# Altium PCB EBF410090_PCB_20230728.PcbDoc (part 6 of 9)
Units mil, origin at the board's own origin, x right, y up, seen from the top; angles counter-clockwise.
Board outline 5393.69 x 3858.26 mil, 6 copper layers (TOP, GND02, ART03, ART04, PWR05, BOTTOM), stack 47.2 mil thick; 570 components, 437 nets, 2015 pads, 1260 vias.
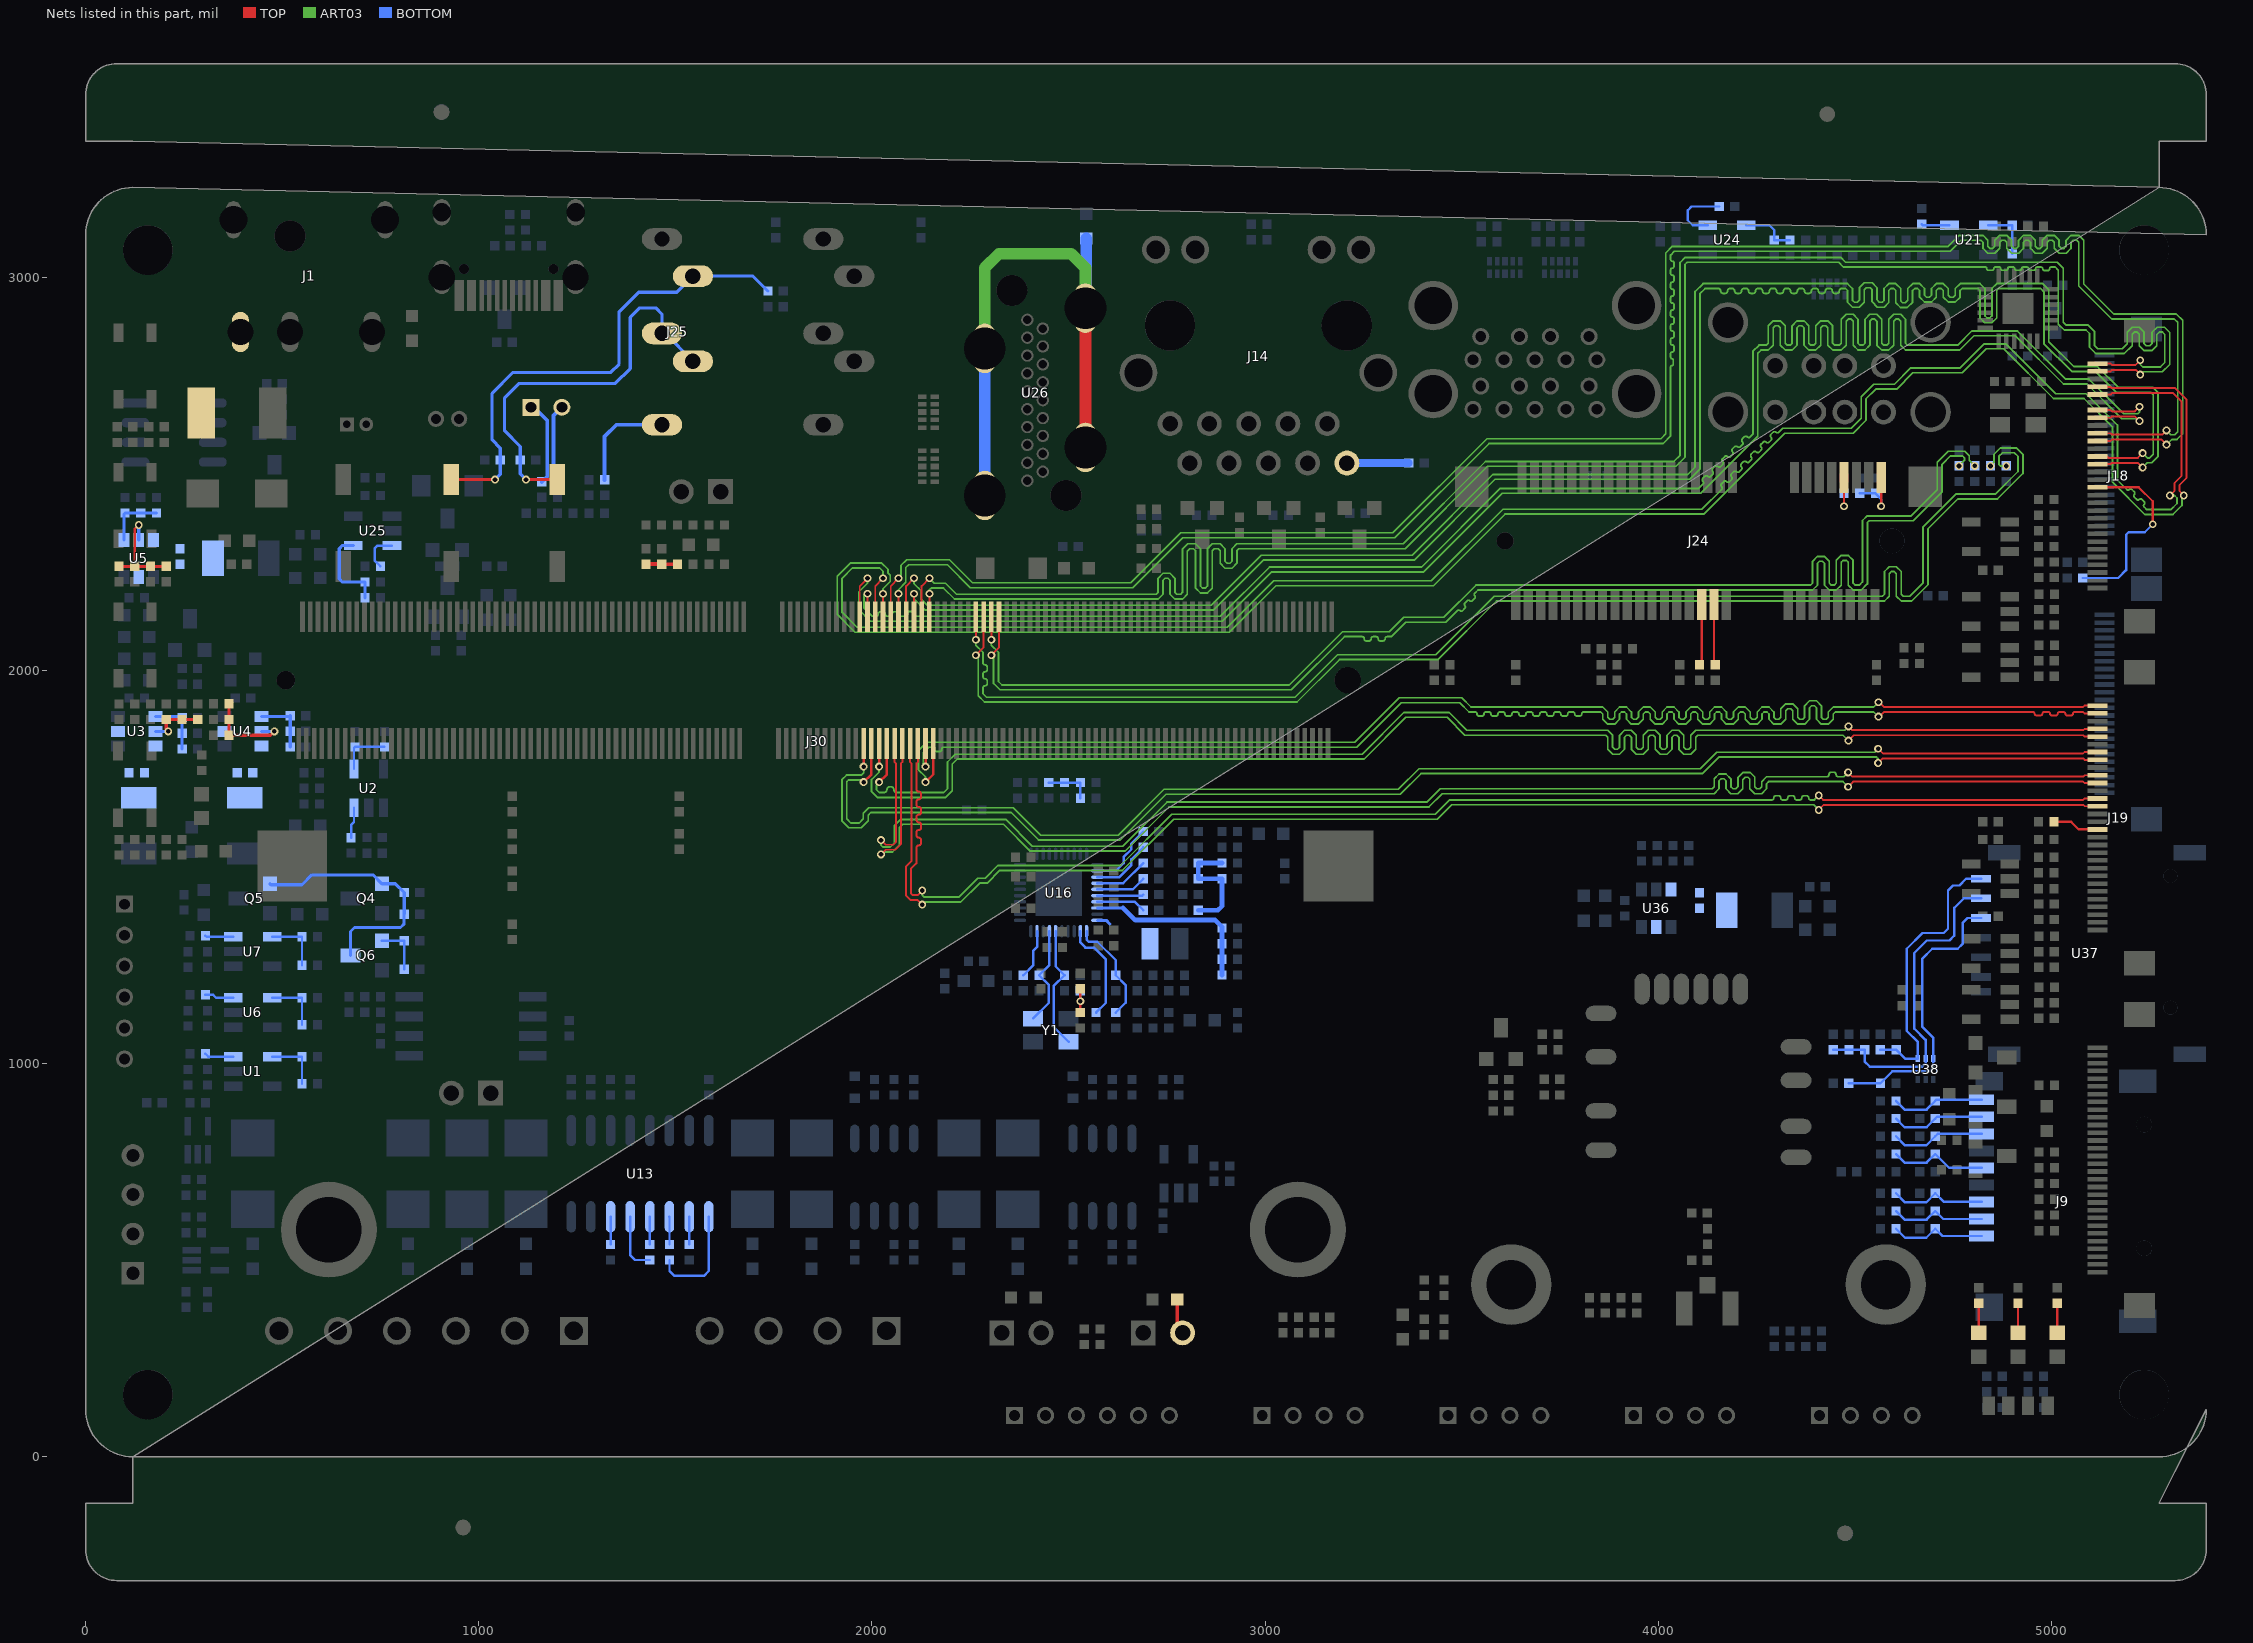
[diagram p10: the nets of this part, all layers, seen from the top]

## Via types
v1: diameter 20, hole 12, TOP to BOTTOM, 1260 vias

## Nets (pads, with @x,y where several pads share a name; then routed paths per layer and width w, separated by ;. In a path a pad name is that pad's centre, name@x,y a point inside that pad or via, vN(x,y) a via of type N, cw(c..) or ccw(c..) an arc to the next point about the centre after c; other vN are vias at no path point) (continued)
MIPI_CSI_RX_D2N: J30.91 R179.1 R181.1 | length 3498.5
  TOP w4.88: v1(2264.25,2038.7) 2283.93,2058.38 J30.91@2283.93,2136.54
  ART03 w4.44: v1(2264.25,2038.7) 2270.03,2032.92 2270.03,1935.72 2286.19,1919.56 3081.16,1919.56 3189.16,2027.56 3439.56,2027.56 3588.46,2176.46 4575.33,2176.46 4587.81,2188.94 4587.81,2246.36 4593.01,2251.56 4600.37,2251.56 4605.57,2246.36 4605.57,2188.94 4618.05,2176.46 4644.46,2176.46 4686,2218 4686,2360.4 4761.6,2436 4862.6,2436 4927.44,2500.84 4927.44,2549.56 4911,2566 4870.5,2566 4854,2549.5 4854,2528.68 v1(4845,2519.68)
MIPI_CSI_RX_D2P: J30.93 R177.1 R178.1 | length 3449.3
  TOP w4.88: v1(2264.25,2078.07) J30.93@2264.25,2136.54
  ART03 w4.44: v1(2264.25,2078.07) 2264.25,2064.47 2282.47,2046.25 2282.47,2019.45 ccw(c2287.73,2019.45) 2287.73,2014.19 cw(c2287.74,2008.93) 2293,2008.93 2293,2001.69 cw(c2287.74,2001.69) 2287.74,1996.43 ccw(c2287.73,1991.17) 2282.47,1991.17 2282.47,1983.93 ccw(c2287.73,1983.93) 2287.73,1978.67 cw(c2287.74,1973.41) 2293,1973.41 2293,1966.17 cw(c2287.74,1966.17) 2287.74,1960.91 ccw(c2287.73,1955.65) 2282.47,1955.65 2282.47,1940.88 2291.35,1932 3076,1932 3184,2040 3434.4,2040 3583.3,2188.9 4570.17,2188.9 4575.37,2194.1 4575.37,2251.52 4587.85,2264 4605.53,2264 4618.01,2251.52 4618.01,2194.1 4623.21,2188.9 4639.3,2188.9 4673.56,2223.16 4673.56,2365.56 4756.44,2448.44 4857.44,2448.44 4915,2506 4915,2544.4 4905.84,2553.56 4875.66,2553.56 4866.44,2544.34 4866.44,2524.22 4870.98,2519.68 v1(4885,2519.68)
MIPI_CSI_RX_D3N: J30.87 R185.1 R186.1 | length 3365.8
  TOP w4.88: v1(2303.62,2038.7) 2323.3,2058.38 J30.87@2323.3,2136.54
  ART03 w4.44: v1(2303.62,2038.7) 2309.4,2032.92 2309.4,1966.72 2325.56,1950.56 3066.56,1950.56 3202,2086 3246.55,2086 cw(c3246.55,2080.5) 3252.05,2080.5 ccw(c3257.55,2080.5) 3257.55,2075 3264.31,2075 ccw(c3264.31,2080.5) 3269.81,2080.5 cw(c3275.31,2080.5) 3275.31,2086 3282.07,2086 cw(c3282.07,2080.5) 3287.57,2080.5 ccw(c3293.07,2080.5) 3293.07,2075 3299.83,2075 ccw(c3299.83,2080.5) 3305.33,2080.5 cw(c3310.83,2080.5) 3310.83,2086 3321,2086 3357.56,2122.56 3459.56,2122.56 3489.03,2152.03 cw(c3492.28,2148.79) 3495.53,2152.03 ccw(c3498.78,2155.27) 3502.03,2152.03 3508.09,2158.09 ccw(c3504.85,2161.34) 3508.09,2164.59 cw(c3511.33,2167.84) 3508.09,2171.09 3514.15,2177.15 cw(c3517.4,2173.91) 3520.65,2177.15 ccw(c3523.9,2180.39) 3527.15,2177.15 3533.21,2183.21 ccw(c3529.97,2186.46) 3533.21,2189.71 cw(c3536.45,2192.96) 3533.21,2196.21 3541.56,2204.56 4392.46,2204.56 4404.94,2217.04 4404.94,2272.36 4410.14,2277.56 4417.5,2277.56 4422.7,2272.36 4422.7,2217.04 4435.18,2204.56 4452.86,2204.56 4465.34,2217.04 4465.34,2275.12 4469.78,2279.56 4478.66,2279.56 4483.1,2275.12 4483.1,2217.04 4495.58,2204.56 4516.56,2204.56 4532,2220 4532,2376.12 4536.44,2380.56 4648.55,2380.56 4722,2454.01 4722,2524.4 4742.88,2545.28 4774.34,2545.28 4778.78,2540.84 4778.78,2534.1 4765,2520.32 v1(4765,2519.68)
MIPI_CSI_RX_D3P: J30.89 R183.1 R184.1 | length 3316
  TOP w4.88: v1(2303.62,2078.07) J30.89@2303.62,2136.54
  ART03 w4.44: v1(2303.62,2078.07) 2303.62,2064.47 2321.84,2046.25 2321.84,1971.88 2330.72,1963 3061.4,1963 3196.84,2098.44 3315.84,2098.44 3352.4,2135 3454.4,2135 3536.4,2217 4387.3,2217 4392.5,2222.2 4392.5,2277.52 4404.98,2290 4422.66,2290 4435.14,2277.52 4435.14,2222.2 4440.34,2217 4447.7,2217 4452.9,2222.2 4452.9,2280.28 4464.62,2292 4483.82,2292 4495.54,2280.28 4495.54,2222.2 4500.74,2217 4511.4,2217 4519.56,2225.16 4519.56,2381.28 4531.28,2393 4643.39,2393 4709.56,2459.17 4709.56,2529.56 4737.72,2557.72 4779.5,2557.72 4791.22,2546 4791.22,2534.1 v1(4805,2520.32)
MIPI_DSI_TX0_CLKN: J18.24 J30.121 | length 4810.6
  TOP w4.88: J30.121@1988.66,2136.54 v1(1988.66,2195.01) ; J18.24@5117.47,2662.33 5150.56,2662.33 5153.96,2658.93 5212.18,2658.93 v1(5224,2670.75)
  ART03 w4.44: v1(1988.66,2195.01) 1983.88,2195.01 1979.44,2190.57 1979.44,2159.16 2000.8,2137.8 2010.24,2137.8 ccw(c2010.24,2143.4) 2015.84,2143.4 cw(c2021.44,2143.4) 2021.44,2149 2028,2149 cw(c2028,2143.4) 2033.6,2143.4 ccw(c2039.2,2143.4) 2039.2,2137.8 2045.76,2137.8 ccw(c2045.76,2143.4) 2051.36,2143.4 cw(c2056.96,2143.4) 2056.96,2149 2063.52,2149 cw(c2063.52,2143.4) 2069.12,2143.4 ccw(c2074.72,2143.4) 2074.72,2137.8 2084.16,2137.8 ccw(c2084.16,2143.9) 2090.26,2143.9 cw(c2096.36,2143.9) 2096.36,2150 2101.92,2150 cw(c2101.92,2143.9) 2108.02,2143.9 ccw(c2114.12,2143.9) 2114.12,2137.8 2886.2,2137.8 3011.4,2263 3398,2263 3598,2463 4103,2463 4113.49,2473.49 ccw(c4109.74,2477.24) 4113.48,2480.99 cw(c4117.23,2484.74) 4113.48,2488.49 4118.54,2493.55 cw(c4122.29,2489.8) 4126.04,2493.55 ccw(c4129.8,2497.29) 4133.55,2493.55 4138.61,2498.61 ccw(c4134.86,2502.36) 4138.6,2506.11 cw(c4142.35,2509.86) 4138.6,2513.61 4143.66,2518.67 cw(c4147.41,2514.92) 4151.16,2518.67 ccw(c4154.92,2522.41) 4158.67,2518.67 4163.73,2523.73 ccw(c4159.98,2527.48) 4163.72,2531.23 cw(c4167.47,2534.98) 4163.72,2538.73 4168.78,2543.79 cw(c4172.53,2540.04) 4176.28,2543.79 ccw(c4180.04,2547.53) 4183.79,2543.79 4188.85,2548.85 ccw(c4185.1,2552.6) 4188.84,2556.35 cw(c4192.59,2560.1) 4188.84,2563.85 4193.9,2568.91 cw(c4197.65,2565.16) 4201.4,2568.91 ccw(c4205.16,2572.65) 4208.91,2568.91 4213.97,2573.97 ccw(c4210.22,2577.72) 4213.96,2581.47 cw(c4217.71,2585.22) 4213.96,2588.97 4219.02,2594.03 cw(c4222.77,2590.28) 4226.52,2594.03 ; 4226.53,2594.02 ccw(c4230.28,2597.77) 4234.03,2594.03 4240.72,2600.72 4240.72,2811.72 4256.44,2827.44 4274.86,2827.44 4280.06,2832.64 4280.06,2876.52 4292.54,2889 4310.22,2889 4322.7,2876.52 4322.7,2832.64 4327.9,2827.44 4335.26,2827.44 4340.46,2832.64 4340.46,2876.52 4352.94,2889 4370.62,2889 4383.1,2876.52 4383.1,2832.64 4388.3,2827.44 4395.66,2827.44 4400.86,2832.64 4400.86,2876.52 4413.34,2889 4431.02,2889 4443.5,2876.52 4443.5,2832.64 4448.7,2827.44 4460.27,2827.44 4465.47,2832.64 4465.47,2893.52 4477.95,2906 4495.63,2906 4508.11,2893.52 4508.11,2832.64 4513.31,2827.44 4520.67,2827.44 4525.87,2832.64 4525.87,2893.52 4538.35,2906 4556.03,2906 4568.51,2893.52 4568.51,2832.64 4573.71,2827.44 4581.07,2827.44 4586.27,2832.64 4586.27,2893.52 4598.75,2906 4616.43,2906 4628.91,2893.52 4628.91,2832.64 4634.11,2827.44 4761.84,2827.44 4797.84,2863.44 4913.56,2863.44 5036,2741 5095.6,2741 5183.89,2652.71 5219.56,2652.71 5224,2657.15 v1(5224,2670.75)
MIPI_DSI_TX0_CLKP: J18.23 J30.123 | length 4807.4
  TOP w4.88: J30.123@1968.97,2136.54 1968.97,2214.69 v1(1988.66,2234.38) ; J18.23@5117.47,2642.64 5150.55,2642.64 5153.96,2646.05 5212.19,2646.05 v1(5224,2634.24)
  ART03 w4.44: v1(1988.66,2234.38) 1988.66,2221.66 1967,2200 1967,2154 1995.64,2125.36 2891.36,2125.36 3016.56,2250.56 3403.16,2250.56 3603.16,2450.56 4108.16,2450.56 4253.16,2595.56 4253.16,2806.56 4261.6,2815 4280.02,2815 4292.5,2827.48 4292.5,2871.36 4297.7,2876.56 4305.06,2876.56 4310.26,2871.36 4310.26,2827.48 4322.74,2815 4340.42,2815 4352.9,2827.48 4352.9,2871.36 4358.1,2876.56 4365.46,2876.56 4370.66,2871.36 4370.66,2827.48 4383.14,2815 4400.82,2815 4413.3,2827.48 4413.3,2871.36 4418.5,2876.56 4425.86,2876.56 4431.06,2871.36 4431.06,2827.48 4443.54,2815 4465.43,2815 4477.91,2827.48 4477.91,2888.36 4483.11,2893.56 4490.47,2893.56 4495.67,2888.36 4495.67,2827.48 4508.15,2815 4525.83,2815 4538.31,2827.48 4538.31,2888.36 4543.51,2893.56 4550.87,2893.56 4556.07,2888.36 4556.07,2827.48 4568.55,2815 4586.23,2815 4598.71,2827.48 4598.71,2888.36 4603.91,2893.56 4611.27,2893.56 4616.47,2888.36 4616.47,2827.48 4628.95,2815 4767,2815 4803,2851 4908.4,2851 5030.84,2728.56 5090.44,2728.56 5178.73,2640.27 5217.97,2640.27 v1(5224,2634.24)
MIPI_DSI_TX0_D0N: J18.27 J30.117 | length 4936.3
  TOP w4.88: J30.117@2028.03,2136.54 v1(2028.03,2195.01) ; J18.27@5117.47,2721.38 5150.56,2721.38 5153.96,2717.98 5315.02,2717.98 5344.14,2688.86 5344.14,2490.14 5326,2472 5326,2455.87 v1(5336.69,2445.18)
  ART03 w4.44: v1(2028.03,2195.01) 2028.03,2208.03 2046.25,2226.25 2046.25,2231.61 2046.26,2241.92 2041,2247.18 2041,2256.6 2024.6,2273 1945,2273 1911.56,2239.56 1911.56,2142.44 1956.74,2097.26 2909.26,2097.26 3027.56,2215.56 3428.16,2215.56 3610.16,2397.56 4116.16,2397.56 4322.16,2603.56 4495.56,2603.56 4528.44,2636.44 4528.44,2690.84 4553.16,2715.56 4606.15,2715.56 4647.59,2757 4773,2757 4834,2818 4879,2818 5005.44,2691.56 5082.84,2691.56 5155.56,2618.84 5155.56,2478.44 5237.44,2396.56 5309.07,2396.56 5332,2419.49 5332,2440.49 v1(5336.69,2445.18)
MIPI_DSI_TX0_D0P: J18.26 J30.119 | length 4937.7
  TOP w4.88: J30.119@2008.34,2136.54 2008.34,2214.69 v1(2028.03,2234.38) ; J18.26@5117.47,2701.7 5150.56,2701.7 5153.96,2705.1 5309.68,2705.1 5331.26,2683.52 5331.26,2495.48 5313.12,2477.34 5313.12,2456.99 v1(5301.31,2445.18)
  ART03 w4.44: v1(2028.03,2234.38) 2028.03,2251.97 2019.44,2260.56 1950.16,2260.56 1924,2234.4 1924,2147.6 1961.9,2109.7 2904.1,2109.7 3022.4,2228 3423,2228 3605,2410 4111,2410 4161.14,2460.14 ccw(c4157.39,2463.89) 4161.14,2467.64 cw(c4164.89,2471.39) 4161.14,2475.14 4166.2,2480.2 cw(c4169.95,2476.45) 4173.7,2480.2 ccw(c4177.45,2483.95) 4181.2,2480.2 4186.26,2485.26 ccw(c4182.51,2489.01) 4186.26,2492.76 cw(c4190.01,2496.51) 4186.26,2500.26 4191.32,2505.32 cw(c4195.07,2501.57) 4198.82,2505.32 ccw(c4202.57,2509.07) 4206.32,2505.32 4211.38,2510.38 ccw(c4207.63,2514.13) 4211.38,2517.88 cw(c4215.13,2521.63) 4211.38,2525.38 4216.44,2530.44 cw(c4220.19,2526.69) 4223.94,2530.44 ccw(c4227.69,2534.19) 4231.44,2530.44 4236.5,2535.5 ccw(c4232.75,2539.25) 4236.5,2543 cw(c4240.25,2546.75) 4236.5,2550.5 4241.56,2555.56 cw(c4245.31,2551.81) 4249.06,2555.56 ccw(c4252.81,2559.31) 4256.56,2555.56 4261.62,2560.62 ccw(c4257.87,2564.37) 4261.62,2568.12 cw(c4265.37,2571.87) 4261.62,2575.62 4266.68,2580.68 cw(c4270.43,2576.93) 4274.18,2580.68 ccw(c4277.93,2584.43) 4281.68,2580.68 4286.74,2585.74 ccw(c4282.99,2589.49) 4286.74,2593.24 cw(c4290.49,2596.99) 4286.74,2600.74 4291.8,2605.8 cw(c4295.55,2602.05) 4299.3,2605.8 ccw(c4303.05,2609.55) 4306.8,2605.8 4317,2616 4490.4,2616 4516,2641.6 4516,2696 4548,2728 4600.99,2728 4642.43,2769.44 4767.84,2769.44 4828.84,2830.44 4884.16,2830.44 5010.6,2704 5088,2704 5168,2624 5168,2483.6 5191.54,2460.06 ccw(c5194.88,2463.41) 5198.22,2460.06 ; 5198.24,2460.08 cw(c5201.58,2456.73) 5204.92,2460.08 5210.8,2454.2 cw(c5207.45,2450.86) 5210.8,2447.52 ccw(c5214.13,2444.16) 5210.78,2440.82 5216.66,2434.94 ccw(c5220,2438.29) 5223.34,2434.94 cw(c5226.7,2431.61) 5230.04,2434.96 5235.92,2429.08 cw(c5232.57,2425.74) 5235.92,2422.4 ccw(c5239.25,2419.04) 5235.9,2415.7 5242.6,2409 5303.91,2409 5319.56,2424.65 5319.56,2438.45 5312.83,2445.18 v1(5301.31,2445.18)
MIPI_DSI_TX0_D1N: J18.21 J30.113 | length 4934.4
  TOP w4.88: J30.113@2067.4,2136.54 v1(2067.4,2195.01) ; J18.21@5117.47,2603.27 5150.56,2603.27 5153.96,2599.87 5282.18,2599.87 v1(5293,2610.69)
  ART03 w4.44: v1(2067.4,2195.01) 2067.4,2205.4 2086,2224 2086,2261.68 2093.32,2269 2192,2269 2250.44,2210.56 2663.56,2210.56 2790.56,2337.56 3330.16,2337.56 3569.6,2577 4012,2577 4031.44,2596.44 4031.44,2772.03 cw(c4034.72,2772.03) 4034.72,2775.31 ccw(c4034.72,2778.59) 4038,2778.59 4038,2789.79 ccw(c4034.72,2789.79) 4034.72,2793.07 cw(c4034.72,2796.35) 4031.44,2796.35 4031.44,2805.79 cw(c4035.67,2805.79) 4035.67,2810.02 ccw(c4035.67,2814.25) 4039.9,2814.25 4039.9,2823.55 ccw(c4035.67,2823.55) 4035.67,2827.78 cw(c4035.67,2832.01) 4031.44,2832.01 4031.44,2841.31 cw(c4035.67,2841.31) 4035.67,2845.54 ccw(c4035.67,2849.77) 4039.9,2849.77 4039.9,2859.07 ccw(c4035.67,2859.07) 4035.67,2863.3 cw(c4035.67,2867.53) 4031.44,2867.53 4031.44,2876.83 cw(c4035.67,2876.83) 4035.67,2881.06 ccw(c4035.67,2885.29) 4039.9,2885.29 4039.9,2894.59 ccw(c4035.67,2894.59) 4035.67,2898.82 cw(c4035.67,2903.05) 4031.44,2903.05 4031.44,2912.35 cw(c4035.67,2912.35) 4035.67,2916.58 ccw(c4035.67,2920.81) 4039.9,2920.81 4039.9,2930.11 ccw(c4035.67,2930.11) 4035.67,2934.34 cw(c4035.67,2938.57) 4031.44,2938.57 4031.44,2947.87 cw(c4035.67,2947.87) 4035.67,2952.1 ccw(c4035.67,2956.33) 4039.9,2956.33 4039.9,2965.63 ccw(c4035.67,2965.63) 4035.67,2969.86 cw(c4035.67,2974.09) 4031.44,2974.09 4031.44,2983.39 cw(c4035.67,2983.39) 4035.67,2987.62 ccw(c4035.67,2991.85) 4039.9,2991.85 4039.9,3001.15 ccw(c4035.67,3001.15) 4035.67,3005.38 cw(c4035.67,3009.61) 4031.44,3009.61 4031.44,3018.91 cw(c4035.67,3018.91) 4035.67,3023.14 ccw(c4035.67,3027.37) 4039.9,3027.37 4039.9,3036.67 ccw(c4035.67,3036.67) 4035.67,3040.9 cw(c4035.67,3045.13) 4031.44,3045.13 4031.44,3056.44 4041.1,3066.1 4742.7,3066.1 4770.6,3094 4820.72,3094 4825.92,3088.8 4825.92,3073.48 4838.4,3061 4856.08,3061 4868.56,3073.48 4868.56,3088.8 4873.76,3094 4881.12,3094 4886.32,3088.8 4886.32,3073.48 4898.8,3061 4916.48,3061 4928.96,3073.48 4928.96,3088.8 4934.16,3094 4941.52,3094 4946.72,3088.8 4946.72,3073.48 4959.2,3061 4976.88,3061 4989.36,3073.48 4989.36,3088.8 4994.56,3094 5001.92,3094 5007.12,3088.8 5007.12,3073.48 5019.6,3061 5037.28,3061 5049.76,3073.48 5049.76,3088.8 5054.96,3094 5064.4,3094 5069.56,3088.84 5069.56,2977.84 5153.4,2894 5312.68,2894 5321.56,2885.12 5321.56,2607.17 5314.04,2599.65 5304.04,2599.65 v1(5293,2610.69)
MIPI_DSI_TX0_D1P: J18.20 J30.115 | length 4926.9
  TOP w4.88: J30.115@2047.71,2136.54 2047.71,2214.69 v1(2067.4,2234.38) ; J18.20@5117.47,2583.59 5150.56,2583.59 5153.96,2586.99 5280.19,2586.99 v1(5293,2574.18)
  ART03 w4.44: v1(2067.4,2234.38) 2069.12,2234.38 2073.56,2238.82 2073.56,2266.84 2088.16,2281.44 2197.16,2281.44 2255.6,2223 2658.4,2223 2785.4,2350 3325,2350 3564.44,2589.44 4006.84,2589.44 4019,2601.6 4019,3061.6 4035.94,3078.54 4737.54,3078.54 4765.44,3106.44 4825.88,3106.44 4838.36,3093.96 4838.36,3078.64 4843.56,3073.44 4850.92,3073.44 4856.12,3078.64 4856.12,3093.96 4868.6,3106.44 4886.28,3106.44 4898.76,3093.96 4898.76,3078.64 4903.96,3073.44 4911.32,3073.44 4916.52,3078.64 4916.52,3093.96 4929,3106.44 4946.68,3106.44 4959.16,3093.96 4959.16,3078.64 4964.36,3073.44 4971.72,3073.44 4976.92,3078.64 4976.92,3093.96 4989.4,3106.44 5007.08,3106.44 5019.56,3093.96 5019.56,3078.64 5024.76,3073.44 5032.12,3073.44 5037.32,3078.64 5037.32,3093.96 5049.8,3106.44 5069.56,3106.44 5082,3094 5082,2983 5158.56,2906.44 5317.84,2906.44 5334,2890.28 5334,2602.01 5319.2,2587.21 5306.03,2587.21 v1(5293,2574.18)
MIPI_DSI_TX0_D2N: J18.18 J30.109 | length 4942.7
  TOP w4.88: J30.109@2106.77,2136.54 v1(2106.77,2195.01) ; J18.18@5117.47,2544.22 5141.45,2544.22 5144.85,2540.82 5220.18,2540.82 v1(5232,2552.64)
  ART03 w4.44: v1(2106.77,2195.01) 2106.77,2182.23 2135.54,2153.46 2868.47,2153.46 2995.57,2280.56 3379.15,2280.56 3584.59,2486 4079.99,2486 4106,2512.01 4106,2958.4 4119.16,2971.56 4152.34,2971.56 cw(c4152.34,2965.28) 4158.62,2965.28 ccw(c4164.9,2965.28) 4164.9,2959 4170.1,2959 ccw(c4170.1,2965.28) 4176.38,2965.28 cw(c4182.66,2965.28) 4182.66,2971.56 4187.86,2971.56 cw(c4187.86,2965.28) 4194.14,2965.28 ccw(c4200.42,2965.28) 4200.42,2959 4205.62,2959 ccw(c4205.62,2965.28) 4211.9,2965.28 cw(c4218.18,2965.28) 4218.18,2971.56 4223.38,2971.56 cw(c4223.38,2965.28) 4229.66,2965.28 ccw(c4235.94,2965.28) 4235.94,2959 4241.14,2959 ccw(c4241.14,2965.28) 4247.42,2965.28 cw(c4253.7,2965.28) 4253.7,2971.56 4258.9,2971.56 cw(c4258.9,2965.28) 4265.18,2965.28 ccw(c4271.46,2965.28) 4271.46,2959 4276.66,2959 ccw(c4276.66,2965.28) 4282.94,2965.28 cw(c4289.22,2965.28) 4289.22,2971.56 4294.42,2971.56 cw(c4294.42,2965.28) 4300.7,2965.28 ccw(c4306.98,2965.28) 4306.98,2959 4312.18,2959 ccw(c4312.18,2965.28) 4318.46,2965.28 cw(c4324.74,2965.28) 4324.74,2971.56 4329.94,2971.56 cw(c4329.94,2965.28) 4336.22,2965.28 ccw(c4342.5,2965.28) 4342.5,2959 4347.7,2959 ccw(c4347.7,2965.28) 4353.98,2965.28 cw(c4360.26,2965.28) 4360.26,2971.56 4365.46,2971.56 cw(c4365.46,2965.28) 4371.74,2965.28 ccw(c4378.02,2965.28) 4378.02,2959 4383.22,2959 ccw(c4383.22,2965.28) 4389.5,2965.28 cw(c4395.78,2965.28) 4395.78,2971.56 4400.98,2971.56 cw(c4400.98,2965.28) 4407.26,2965.28 ccw(c4413.54,2965.28) 4413.54,2959 4418.74,2959 ccw(c4418.74,2965.28) 4425.02,2965.28 cw(c4431.3,2965.28) 4431.3,2971.56 4436.5,2971.56 cw(c4436.5,2965.28) 4442.78,2965.28 ccw(c4449.06,2965.28) 4449.06,2959 4454.26,2959 ccw(c4454.26,2965.28) 4460.54,2965.28 cw(c4466.82,2965.28) 4466.82,2971.56 4476.26,2971.56 4481.46,2966.36 4481.46,2936.48 4493.94,2924 4511.62,2924 4524.1,2936.48 4524.1,2968.36 4529.3,2973.56 4538.74,2973.56 4543.94,2968.36 4543.94,2937.48 4557.42,2924 4574.86,2924 4586.58,2935.72 4586.58,2966.36 4591.78,2971.56 4599.14,2971.56 4604.34,2966.36 4604.34,2934.72 4616.06,2923 4633.5,2923 4646.98,2936.48 4646.98,2966.36 4652.18,2971.56 4659.54,2971.56 4664.74,2966.36 4664.74,2949.48 4677.22,2937 4694.9,2937 4707.38,2949.48 4707.38,2966.36 4712.58,2971.56 4719.94,2971.56 4725.14,2966.36 4725.14,2949.48 4737.62,2937 4755.3,2937 4767.78,2949.48 4767.78,2966.36 4772.98,2971.56 4813.25,2971.56 4818.45,2966.36 4818.45,2896.48 4830.93,2884 4848.61,2884 4861.09,2896.48 4861.09,2966.36 4866.29,2971.56 4972.84,2971.56 4981,2963.4 4981,2831 5051.44,2760.56 5111.84,2760.56 5164.84,2707.56 5252.84,2707.56 5258.88,2701.52 5258.88,2549.48 5250,2540.6 5244.04,2540.6 v1(5232,2552.64)
MIPI_DSI_TX0_D2P: J18.17 J30.111 | length 4926.3
  TOP w4.88: J30.111@2087.08,2136.54 2087.08,2214.69 v1(2106.77,2234.38) ; J18.17@5117.47,2524.53 5150.55,2524.53 5153.96,2527.94 5220.19,2527.94 v1(5232,2516.13)
  ART03 w4.44: v1(2106.77,2234.38) 2106.77,2220.78 2124.99,2202.56 2124.99,2181.61 2140.7,2165.9 2863.31,2165.9 2990.41,2293 3373.99,2293 3579.43,2498.44 4074.83,2498.44 4093.56,2517.17 4093.56,2963.56 4114,2984 4481.42,2984 4493.9,2971.52 4493.9,2941.64 4499.1,2936.44 4506.46,2936.44 4511.66,2941.64 4511.66,2973.52 4524.14,2986 4543.9,2986 4556.38,2973.52 4556.38,2942.64 4562.58,2936.44 4569.7,2936.44 4574.14,2940.88 4574.14,2971.52 4586.62,2984 4604.3,2984 4616.78,2971.52 4616.78,2939.88 4621.22,2935.44 4628.34,2935.44 4634.54,2941.64 4634.54,2971.52 4647.02,2984 4664.7,2984 4677.18,2971.52 4677.18,2954.64 4682.38,2949.44 4689.74,2949.44 4694.94,2954.64 4694.94,2971.52 4707.42,2984 4725.1,2984 4737.58,2971.52 4737.58,2954.64 4742.78,2949.44 4750.14,2949.44 4755.34,2954.64 4755.34,2971.52 4767.82,2984 4818.41,2984 4830.89,2971.52 4830.89,2901.64 4836.09,2896.44 4843.45,2896.44 4848.65,2901.64 4848.65,2971.52 4861.13,2984 4978,2984 4993.44,2968.56 4993.44,2836.16 5056.6,2773 5117,2773 5170,2720 5258,2720 5271.32,2706.68 5271.32,2544.32 5255.16,2528.16 5244.03,2528.16 v1(5232,2516.13)
MIPI_DSI_TX0_D3N: J18.30 J30.105 | length 4923.8
  TOP w4.88: J30.105@2146.14,2136.54 v1(2146.14,2195.01) ; J18.30@5117.47,2780.44 5150.56,2780.44 5153.96,2777.04 5214.18,2777.04 v1(5226,2788.86)
  ART03 w4.44: v1(2146.14,2195.01) 2146.14,2205.03 2150.58,2209.47 2181.93,2209.47 2209.84,2181.56 2727.8,2181.56 2740.28,2194.04 2740.28,2229.36 2745.48,2234.56 2752.84,2234.56 2758.04,2229.36 2758.04,2194.04 2770.52,2181.56 2790.28,2181.56 2802,2193.28 2802,2303 2808.46,2309.46 2817.9,2309.46 2823.1,2304.26 2823.1,2209.48 2835.58,2197 2853.26,2197 2865.74,2209.48 2865.74,2304.26 2870.94,2309.46 2880.38,2309.46 2885.58,2304.26 2885.58,2272.48 2898.06,2260 2915.74,2260 2928.22,2272.48 2928.22,2304.26 2933.42,2309.46 3356.06,2309.46 3565.6,2519 4045,2519 4068,2542 4068,3032.4 4073.6,3038 4459,3038 4471,3026 4831.62,3026 cw(c4831.62,3022) 4835.62,3022 ccw(c4839.62,3022) 4839.62,3018 4849.38,3018 ccw(c4849.38,3022) 4853.38,3022 cw(c4857.38,3022) 4857.38,3026 4867.14,3026 cw(c4867.14,3022) 4871.14,3022 ccw(c4875.14,3022) 4875.14,3018 4884.9,3018 ccw(c4884.9,3022) 4888.9,3022 cw(c4892.9,3022) 4892.9,3026 4902.66,3026 cw(c4902.66,3022) 4906.66,3022 ccw(c4910.66,3022) 4910.66,3018 4920.42,3018 ccw(c4920.42,3022) 4924.42,3022 cw(c4928.42,3022) 4928.42,3026 4938.18,3026 cw(c4938.18,3022) 4942.18,3022 ccw(c4946.18,3022) 4946.18,3018 4955.94,3018 ccw(c4955.94,3022) 4959.94,3022 cw(c4963.94,3022) 4963.94,3026 4973.7,3026 cw(c4973.7,3022) 4977.7,3022 ccw(c4982.7,3022) 4982.7,3017 4990.46,3017 ccw(c4990.46,3022) 4995.46,3022 cw(c4999.46,3022) 4999.46,3026 5009.4,3026 5017.56,3017.84 5017.56,2880.84 5032.4,2866 5088.12,2866 5097,2857.12 5097,2822.16 5113.16,2806 5185.52,2806 5205.56,2826.04 5205.56,2855.36 5210.76,2860.56 5218.12,2860.56 5223.32,2855.36 5223.32,2826.04 5235.8,2813.56 5255.56,2813.56 5268,2826 5268,2854.4 5274.16,2860.56 5282.44,2860.56 5288.56,2854.44 5288.56,2783.16 5277.22,2771.82 5232.18,2771.82 5226,2778 v1(5226,2788.86)
MIPI_DSI_TX0_D3P: J18.29 J30.107 | length 4948.5
  TOP w4.88: J30.107@2126.45,2136.54 2126.45,2214.69 v1(2146.14,2234.38) ; J18.29@5117.47,2760.75 5150.55,2760.75 5153.96,2764.16 5214.19,2764.16 v1(5226,2752.35)
  ART03 w4.44: v1(2146.14,2234.38) 2158.61,2221.91 2187.09,2221.91 2215,2194 2722.64,2194 2727.84,2199.2 2727.84,2234.52 2740.32,2247 2758,2247 2770.48,2234.52 2770.48,2199.2 2775.68,2194 2785.12,2194 2789.56,2198.44 2789.56,2308.16 2803.3,2321.9 2823.06,2321.9 2835.54,2309.42 2835.54,2214.64 2840.74,2209.44 2848.1,2209.44 2853.3,2214.64 2853.3,2309.42 2865.78,2321.9 2885.54,2321.9 2898.02,2309.42 2898.02,2277.64 2903.22,2272.44 2910.58,2272.44 2915.78,2277.64 2915.78,2309.42 2928.26,2321.9 3350.9,2321.9 3560.44,2531.44 4039.84,2531.44 4055.56,2547.16 4055.56,3037.56 4068.44,3050.44 4464.16,3050.44 4476.16,3038.44 5014.56,3038.44 5030,3023 5030,2886 5037.56,2878.44 5093.28,2878.44 5109.44,2862.28 5109.44,2827.32 5118.32,2818.44 5180.36,2818.44 5193.12,2831.2 5193.12,2860.52 5205.6,2873 5223.28,2873 5235.76,2860.52 5235.76,2831.2 5240.96,2826 5250.4,2826 5255.56,2831.16 5255.56,2859.56 5269,2873 5287.6,2873 5301,2859.6 5301,2778 5282.38,2759.38 5233.03,2759.38 v1(5226,2752.35)
MIPI_DSI_TX1_CLKN: J19.24 J30.120 | length 3584.2
  TOP w4.88: v1(4559.26,1800.75) 4571.08,1788.93 5080.98,1788.93 5084.38,1792.33 J19.24@5117.47,1792.33
  TOP w6.16: v1(1978.82,1715.86) 1998.5,1735.54 J30.120@1998.5,1813.7
  ART03 w4.44: v1(1978.82,1715.86) 1973.35,1721.33 1940.44,1721.33 1936,1716.89 1936,1622.44 1946.44,1612 1967.56,1612 1978,1622.44 1978,1637 1992,1651 2359,1651 2429,1581 2626.4,1581 2742.84,1697.44 3338.84,1697.44 3391.4,1750 4106.4,1750 4148.4,1792 4550.51,1792 v1(4559.26,1800.75)
MIPI_DSI_TX1_CLKP: J19.23 J30.122 | length 3602.6
  TOP w4.88: v1(4559.26,1764.24) 4571.07,1776.05 5080.98,1776.05 5084.39,1772.64 J19.23@5117.47,1772.64
  TOP w6.16: v1(1978.82,1755.23) J30.122@1978.82,1813.7
  ART03 w4.44: v1(1978.82,1755.23) 1978.82,1739.83 1972.76,1733.77 1935.28,1733.77 1923.56,1722.05 1923.56,1617.28 1941.28,1599.56 1972.72,1599.56 1990.44,1617.28 1990.44,1631.84 1997.16,1638.56 2353.84,1638.56 2423.84,1568.56 2631.56,1568.56 2748,1685 3344,1685 3396.56,1737.56 4111.56,1737.56 4153.56,1779.56 4554.82,1779.56 4559.26,1775.12 v1(4559.26,1764.24)
MIPI_DSI_TX1_D0N: J19.27 J30.116 | length 3709.8
  TOP w4.88: v1(4484,1857.8) 4493.82,1847.98 5080.98,1847.98 5084.38,1851.38 J19.27@5117.47,1851.38
  TOP w6.16: v1(2018.19,1715.86) 2037.87,1735.54 J30.116@2037.87,1813.7
  ART03 w4.44: v1(2018.19,1715.86) 2011.44,1709.11 2011.44,1696.88 2018.88,1689.44 2030.68,1689.44 ccw(c2030.68,1696.72) 2037.96,1696.72 cw(c2045.24,1696.72) 2045.24,1704 2048.44,1704 cw(c2048.44,1696.72) 2055.72,1696.72 ccw(c2063,1696.72) 2063,1689.44 2182.56,1689.44 2192,1698.88 2192,1767 2212,1787 3247,1787 3353,1893 3468,1893 3513.24,1847.76 3871.34,1847.76 3883.82,1835.28 3883.82,1804.64 3889.02,1799.44 3896.38,1799.44 3901.58,1804.64 3901.58,1835.28 3914.06,1847.76 3931.74,1847.76 3944.22,1835.28 3944.22,1804.64 3949.42,1799.44 3956.78,1799.44 3961.98,1804.64 3961.98,1835.28 3974.46,1847.76 3992.14,1847.76 4004.62,1835.28 4004.62,1804.64 4009.82,1799.44 4017.18,1799.44 4022.38,1804.64 4022.38,1835.28 4034.86,1847.76 4052.54,1847.76 4065.02,1835.28 4065.02,1804.64 4070.22,1799.44 4077.58,1799.44 4082.78,1804.64 4082.78,1835.28 4095.26,1847.76 4473.96,1847.76 v1(4484,1857.8)
MIPI_DSI_TX1_D0P: J19.26 J30.118 | length 3714.1
  TOP w4.88: v1(4484,1821.29) 4497.81,1835.1 5080.98,1835.1 5084.38,1831.7 J19.26@5117.47,1831.7
  TOP w6.16: v1(2018.19,1755.23) J30.118@2018.19,1813.7
  ART03 w4.44: v1(2018.19,1755.23) 2018.19,1741.63 1999,1722.44 1999,1691.72 2013.72,1677 2187.72,1677 2204.44,1693.72 2204.44,1761.84 2217.16,1774.56 3252.16,1774.56 3358.16,1880.56 3462.84,1880.56 3508.08,1835.32 3866.18,1835.32 3871.38,1830.12 3871.38,1799.48 3883.86,1787 3901.54,1787 3914.02,1799.48 3914.02,1830.12 3919.22,1835.32 3926.58,1835.32 3931.78,1830.12 3931.78,1799.48 3944.26,1787 3961.94,1787 3974.42,1799.48 3974.42,1830.12 3979.62,1835.32 3986.98,1835.32 3992.18,1830.12 3992.18,1799.48 4004.66,1787 4022.34,1787 4034.82,1799.48 4034.82,1830.12 4040.02,1835.32 4047.38,1835.32 4052.58,1830.12 4052.58,1799.48 4065.06,1787 4082.74,1787 4095.22,1799.48 4095.22,1830.12 4100.42,1835.32 4469.97,1835.32 v1(4484,1821.29)
MIPI_DSI_TX1_D1N: J19.21 J30.114 | length 3712.4
  TOP w4.88: v1(2023,1568.23) 2034.57,1556.66 2054.44,1556.66 2060.96,1563.18 2060.96,1763.43 2057.56,1766.83 J30.114@2057.56,1813.7 ; v1(4483,1740.69) 4493.82,1729.87 5080.98,1729.87 5084.38,1733.27 J19.21@5117.47,1733.27
  ART03 w4.44: v1(2023,1568.23) 2023,1555.15 2027.45,1550.7 2046.82,1550.7 2057,1560.88 2057,1604.6 2073.4,1621 2339.84,1621 2407.94,1552.9 2638.3,1552.9 2750.4,1665 3411.4,1665 3445.1,1698.7 4136.95,1698.7 4142.15,1703.9 4142.15,1724.17 4154.63,1736.65 4172.31,1736.65 4184.79,1724.17 4184.79,1703.9 4189.99,1698.7 4197.35,1698.7 4202.55,1703.9 4202.55,1727.17 4216.03,1740.65 4233.47,1740.65 4245.19,1728.93 4245.19,1703.9 4250.39,1698.7 4257.75,1698.7 4262.95,1703.9 4262.95,1717.17 4275.43,1729.65 4428.76,1729.65 ccw(c4428.76,1735.32) 4434.43,1735.32 ; 4434.43,1735.33 cw(c4440.1,1735.33) 4440.1,1741 4446.52,1741 cw(c4446.52,1735.33) 4452.19,1735.33 ; 4452.19,1735.32 ccw(c4457.86,1735.32) 4457.86,1729.65 4471.96,1729.65 v1(4483,1740.69)
MIPI_DSI_TX1_D1P: J19.20 J30.112 | length 3710
  TOP w4.88: v1(2023,1532.21) 2034.57,1543.78 2059.78,1543.78 2073.84,1557.84 2073.84,1763.43 2077.24,1766.83 J30.112@2077.24,1813.7 ; v1(4483,1704.18) 4495.81,1716.99 5080.98,1716.99 5084.38,1713.59 J19.20@5117.47,1713.59
  ART03 w4.44: v1(2023,1532.21) 2029.05,1538.26 2051.98,1538.26 2069.44,1555.72 2069.44,1599.44 2078.56,1608.56 2334.68,1608.56 2402.78,1540.46 2643.46,1540.46 2755.56,1652.56 3416.56,1652.56 3450.26,1686.26 4142.11,1686.26 4154.59,1698.74 4154.59,1719.01 4159.79,1724.21 4167.15,1724.21 4172.35,1719.01 4172.35,1698.74 4184.83,1686.26 4202.51,1686.26 4214.99,1698.74 4214.99,1722.01 4221.19,1728.21 4228.31,1728.21 4232.75,1723.77 4232.75,1698.74 4245.23,1686.26 4262.91,1686.26 4275.39,1698.74 4275.39,1712.01 4280.59,1717.21 4469.97,1717.21 v1(4483,1704.18)
MIPI_DSI_TX1_D2N: J19.18 J30.108 | length 3629.2
  TOP w4.88: J30.108@2116.61,1813.7 2116.61,1766.83 2113.21,1763.43 2113.21,1697.58 ccw(c2119.1,1697.58) 2119.1,1691.69 cw(c2119.11,1685.8) 2125,1685.8 2125,1678.06 cw(c2119.11,1678.06) 2119.11,1672.17 ccw(c2119.1,1666.28) 2113.21,1666.28 2113.21,1658.54 ccw(c2119.1,1658.54) 2119.1,1652.65 cw(c2119.11,1646.76) 2125,1646.76 2125,1639.02 cw(c2119.11,1639.02) 2119.11,1633.13 ccw(c2119.1,1627.24) 2113.21,1627.24 2113.21,1619.5 ccw(c2119.1,1619.5) 2119.1,1613.61 cw(c2119.11,1607.72) 2125,1607.72 2125,1599.98 cw(c2119.11,1599.98) 2119.11,1594.09 ccw(c2119.1,1588.2) 2113.21,1588.2 2113.21,1580.46 ccw(c2119.1,1580.46) 2119.1,1574.57 cw(c2119.11,1568.68) 2125,1568.68 2125,1560.94 cw(c2119.11,1560.94) 2119.11,1555.05 ccw(c2119.1,1549.16) 2113.21,1549.16 2113.21,1509.21 2099,1495 2099,1433.54 2103.88,1428.66 2116.43,1428.66 v1(2128,1440.23) ; v1(4408.26,1681.64) 4419.08,1670.82 5080.98,1670.82 5084.38,1674.22 J19.18@5117.47,1674.22
  ART03 w4.44: v1(2128,1440.23) 2128,1427.99 2132.55,1423.44 2220.84,1423.44 2268.84,1471.44 2287.84,1471.44 2320.18,1503.78 2632.18,1503.78 2762.4,1634 3433,1634 3469.6,1670.6 4288.58,1670.6 ccw(c4288.58,1675.8) 4293.78,1675.8 cw(c4298.98,1675.8) 4298.98,1681 4306.34,1681 cw(c4306.34,1675.8) 4311.54,1675.8 ccw(c4316.74,1675.8) 4316.74,1670.6 4324.1,1670.6 ccw(c4324.1,1675.8) 4329.3,1675.8 cw(c4334.5,1675.8) 4334.5,1681 4341.86,1681 cw(c4341.86,1675.8) 4347.06,1675.8 ccw(c4352.26,1675.8) 4352.26,1670.6 4359.62,1670.6 ccw(c4359.62,1675.8) 4364.82,1675.8 cw(c4370.02,1675.8) 4370.02,1681 4377.38,1681 cw(c4377.38,1675.8) 4382.58,1675.8 ccw(c4387.78,1675.8) 4387.78,1670.6 4397.22,1670.6 v1(4408.26,1681.64)
MIPI_DSI_TX1_D2P: J19.17 J30.110 | length 3551.4
  TOP w4.88: J30.110@2096.93,1813.7 2096.93,1766.83 2100.33,1763.43 2100.33,1514.55 2086.12,1500.34 2086.12,1428.2 2098.54,1415.78 2116.43,1415.78 v1(2128,1404.21) ; v1(4408.26,1645.13) 4421.07,1657.94 5080.98,1657.94 5084.39,1654.53 J19.17@5117.47,1654.53
  ART03 w4.44: v1(2128,1404.21) 2134.79,1411 2226,1411 2274,1459 2293,1459 2325.34,1491.34 2637.34,1491.34 2767.56,1621.56 3438.16,1621.56 3474.76,1658.16 4395.23,1658.16 v1(4408.26,1645.13)
MIPI_DSI_TX1_D3N: J19.30 J30.104 | length 3729.7
  TOP w4.88: v1(4560.26,1918.86) 4562,1918.86 4573.82,1907.04 5080.98,1907.04 5084.38,1910.44 J19.30@5117.47,1910.44
  TOP w6.16: v1(2136.3,1715.86) 2155.98,1735.54 J30.104@2155.98,1813.7
  ART03 w4.44: v1(2136.3,1715.86) 2136.3,1729.46 2118.08,1747.68 2118.08,1795.68 2139.64,1817.24 3227.64,1817.24 3340.84,1930.44 3500.16,1930.44 3523.78,1906.82 3858.84,1906.82 3871.32,1894.34 3871.32,1881.06 3876.52,1875.86 3883.88,1875.86 3889.08,1881.06 3889.08,1894.34 3901.56,1906.82 3919.24,1906.82 3931.72,1894.34 3931.72,1881.06 3936.92,1875.86 3944.28,1875.86 3949.48,1881.06 3949.48,1894.34 3961.96,1906.82 3979.64,1906.82 3992.12,1894.34 3992.12,1881.06 3997.32,1875.86 4004.68,1875.86 4009.88,1881.06 4009.88,1894.34 4022.36,1906.82 4040.04,1906.82 4052.52,1894.34 4052.52,1881.06 4057.72,1875.86 4065.08,1875.86 4070.28,1881.06 4070.28,1894.34 4082.76,1906.82 4100.44,1906.82 4112.92,1894.34 4112.92,1881.06 4118.12,1875.86 4125.48,1875.86 4130.68,1881.06 4130.68,1894.34 4143.16,1906.82 4160.84,1906.82 4173.32,1894.34 4173.32,1881.06 4178.52,1875.86 4185.88,1875.86 4191.08,1881.06 4191.08,1894.34 4203.56,1906.82 4221.24,1906.82 4233.72,1894.34 4233.72,1881.06 4238.92,1875.86 4246.28,1875.86 4251.48,1881.06 4251.48,1894.34 4263.96,1906.82 4281.64,1906.82 4294.12,1894.34 4294.12,1881.06 4299.32,1875.86 4306.68,1875.86 4311.88,1881.06 4311.88,1902.34 4324.36,1914.82 4342.04,1914.82 4354.52,1902.34 4354.52,1881.06 4359.72,1875.86 4367.08,1875.86 4372.28,1881.06 4372.28,1910.34 4384.76,1922.82 4402.44,1922.82 4414.92,1910.34 4414.92,1881.06 4420.12,1875.86 4427.48,1875.86 4432.68,1881.06 4432.68,1894.34 4445.16,1906.82 4548.22,1906.82 v1(4560.26,1918.86)
MIPI_DSI_TX1_D3P: J19.29 J30.106 | length 3753.8
  TOP w4.88: v1(4560.26,1882.35) 4562,1882.35 4573.81,1894.16 4953.1,1894.16 cw(c4953.1,1889.84) 4957.42,1889.84 ccw(c4961.74,1889.83) 4961.74,1885.51 4972.62,1885.51 ccw(c4972.62,1889.83) 4976.94,1889.83 cw(c4981.26,1889.84) 4981.26,1894.16 4992.14,1894.16 cw(c4992.14,1889.84) 4996.46,1889.84 ccw(c5000.78,1889.83) 5000.78,1885.51 5011.66,1885.51 ccw(c5011.66,1889.83) 5015.98,1889.83 cw(c5020.3,1889.84) 5020.3,1894.16 5031.18,1894.16 cw(c5031.18,1889.84) 5035.5,1889.84 ccw(c5039.82,1889.83) 5039.82,1885.51 5050.7,1885.51 ccw(c5050.7,1889.83) 5055.02,1889.83 cw(c5059.34,1889.84) 5059.34,1894.16 5080.98,1894.16 5084.39,1890.75 J19.29@5117.47,1890.75
  TOP w6.16: v1(2136.3,1755.23) J30.106@2136.3,1813.7
  ART03 w4.44: v1(2136.3,1755.23) 2130.52,1761.01 2130.52,1790.52 2144.8,1804.8 2154.24,1804.8 cw(c2154.24,1799.4) 2159.64,1799.4 ccw(c2165.04,1799.4) 2165.04,1794 2172,1794 ccw(c2172,1799.4) 2177.4,1799.4 cw(c2182.8,1799.4) 2182.8,1804.8 3232.8,1804.8 3346,1918 3495,1918 3518.62,1894.38 3533.78,1894.38 cw(c3533.78,1889.19) 3538.97,1889.19 ccw(c3544.16,1889.19) 3544.16,1884 3551.54,1884 ccw(c3551.54,1889.19) 3556.73,1889.19 cw(c3561.92,1889.19) 3561.92,1894.38 3569.3,1894.38 cw(c3569.3,1889.19) 3574.49,1889.19 ccw(c3579.68,1889.19) 3579.68,1884 3587.06,1884 ccw(c3587.06,1889.19) 3592.25,1889.19 cw(c3597.44,1889.19) 3597.44,1894.38 3604.82,1894.38 cw(c3604.82,1889.19) 3610.01,1889.19 ccw(c3615.2,1889.19) 3615.2,1884 3622.58,1884 ccw(c3622.58,1889.19) 3627.77,1889.19 cw(c3632.96,1889.19) 3632.96,1894.38 3640.34,1894.38 cw(c3640.34,1889.19) 3645.53,1889.19 ccw(c3650.72,1889.19) 3650.72,1884 3658.1,1884 ccw(c3658.1,1889.19) 3663.29,1889.19 cw(c3668.48,1889.19) 3668.48,1894.38 3675.86,1894.38 cw(c3675.86,1889.19) 3681.05,1889.19 ccw(c3686.24,1889.19) 3686.24,1884 3693.62,1884 ccw(c3693.62,1889.19) 3698.81,1889.19 cw(c3704,1889.19) 3704,1894.38 3711.38,1894.38 cw(c3711.38,1889.19) 3716.57,1889.19 ccw(c3721.76,1889.19) 3721.76,1884 3729.14,1884 ccw(c3729.14,1889.19) 3734.33,1889.19 cw(c3739.52,1889.19) 3739.52,1894.38 3746.9,1894.38 cw(c3746.9,1889.19) 3752.09,1889.19 ccw(c3757.28,1889.19) 3757.28,1884 3764.66,1884 ccw(c3764.66,1889.19) 3769.85,1889.19 cw(c3775.04,1889.19) 3775.04,1894.38 3782.42,1894.38 cw(c3782.42,1889.19) 3787.61,1889.19 ccw(c3792.8,1889.19) 3792.8,1884 3800.18,1884 ccw(c3800.18,1889.19) 3805.37,1889.19 cw(c3810.56,1889.19) 3810.56,1894.38 3853.68,1894.38 3858.88,1889.18 3858.88,1875.9 3871.36,1863.42 3889.04,1863.42 3901.52,1875.9 3901.52,1889.18 3906.72,1894.38 3914.08,1894.38 3919.28,1889.18 3919.28,1875.9 3931.76,1863.42 3949.44,1863.42 3961.92,1875.9 3961.92,1889.18 3967.12,1894.38 3974.48,1894.38 3979.68,1889.18 3979.68,1875.9 3992.16,1863.42 4009.84,1863.42 4022.32,1875.9 4022.32,1889.18 4027.52,1894.38 4034.88,1894.38 4040.08,1889.18 4040.08,1875.9 4052.56,1863.42 4070.24,1863.42 4082.72,1875.9 4082.72,1889.18 4087.92,1894.38 4095.28,1894.38 4100.48,1889.18 4100.48,1875.9 4112.96,1863.42 4130.64,1863.42 4143.12,1875.9 4143.12,1889.18 4148.32,1894.38 4155.68,1894.38 4160.88,1889.18 4160.88,1875.9 4173.36,1863.42 4191.04,1863.42 4203.52,1875.9 4203.52,1889.18 4208.72,1894.38 4216.08,1894.38 4221.28,1889.18 4221.28,1875.9 4233.76,1863.42 4251.44,1863.42 4263.92,1875.9 4263.92,1889.18 4269.12,1894.38 4276.48,1894.38 4281.68,1889.18 4281.68,1875.9 4294.16,1863.42 4311.84,1863.42 4324.32,1875.9 4324.32,1897.18 4329.52,1902.38 4336.88,1902.38 4342.08,1897.18 4342.08,1875.9 4354.56,1863.42 4372.24,1863.42 4384.72,1875.9 4384.72,1905.18 4389.92,1910.38 4397.28,1910.38 4402.48,1905.18 4402.48,1875.9 4414.96,1863.42 4432.64,1863.42 4445.12,1875.9 4445.12,1889.18 4450.32,1894.38 4548.23,1894.38 v1(4560.26,1882.35)
N02088: F1.1 J1.4
N03633: C7.1 U3.6
N03641: C7.2 L1.1 U3.2
N03801: C8.2 R4.2 R6.1 U3.4 | length 149.1
  BOTTOM w8: U3.4@177.24,1882.4 242.92,1882.4 R6.1@245.32,1880 R4.2@245.32,1840 C8.2@245.32,1800
N28501: C28.1 U5.6
N28533: C28.2 L3.1 U5.2
N15118698: C4.1 R1.2 U1.4 | length 145.1
  BOTTOM w6.16: U1.4@474.21,1017.4 C4.1@550.32,1017.4 R1.2@550.32,948.42
N15119063: R2.1 U1.3 | length 74.3
  BOTTOM w6.16: R2.1@304.68,1025 312.28,1017.4 U1.3@375.79,1017.4
N15122947: C9.1 R3.2 U2.4 | length 132.1
  BOTTOM w6.16: U2.4@682.6,1749.21 682.6,1802.92 C9.1@685,1805.32 R3.2@760,1805.32
N15123057: R5.1 U2.3 | length 79.3
  BOTTOM w6.16: R5.1@675,1574.68 675,1607 682.6,1614.6 U2.3@682.6,1650.79
N15599533: R96.2 U16.25 | length 128.1
  BOTTOM w6.16: U16.25@2573.43,1442.87 2663.19,1442.87 R96.2@2690.32,1470
N15599537: R97.2 U16.24 | length 138.2
  BOTTOM w6.16: U16.24@2573.43,1458.62 2638.94,1458.62 R97.2@2690.32,1510
N15599541: R99.2 U16.23 | length 156.8
  BOTTOM w6.16: U16.23@2573.43,1474.37 2629.37,1474.37 2660,1505 2660,1519.68 R99.2@2690.32,1550
N15599545: R100.2 U16.22 | length 175.6
  BOTTOM w6.16: U16.22@2573.43,1490.12 2620.12,1490.12 2640,1510 2640,1525 2660,1545 2660,1559.68 R100.2@2690.32,1590
N15599549: R101.2 U16.27 | length 125.7
  BOTTOM w6.16: U16.27@2573.43,1411.38 2668.94,1411.38 R101.2@2690.32,1390
N15599553: R102.2 U16.26 | length 118.1
  BOTTOM w6.16: U16.26@2573.43,1427.13 2687.45,1427.13 R102.2@2690.32,1430
N15599792: R90.2 R91.1 R93.1 R94.1 R95.1 | length 295.9
  BOTTOM w12: R95.1@2829.68,1390 2880,1390 2890.32,1400.32 R91.1@2890.32,1470 R93.1@2829.68,1470 R94.1@2829.68,1510 R90.2@2890.32,1510
N15600759: R106.2 R107.1 R108.1 R109.1 | length 120.5
  BOTTOM w6.16: R108.1@2450,1714.68 R109.1@2490,1714.68 2530,1714.68 R107.1@2530.32,1715 R106.2@2530.32,1675
N15600826: R110.2 R112.2 U16.31 | length 271.2
  BOTTOM w6.16: U16.31@2545.87,1336.57 2545.87,1315.13 2551,1310 2573,1310 2620,1263 R110.2@2620,1224.68 2645,1199.68 2645,1154.68 R112.2@2620,1129.68
N15601838: C83.1 U16.37 Y1.1 | length 260
  BOTTOM w6.16: Y1.1@2409.72,1114.53 2450,1154.81 2450,1199.68 C83.1@2425,1224.68 2451.38,1251.06 U16.37@2451.38,1336.57
N15601846: C84.1 U16.36 Y1.3 | length 317.9
  BOTTOM w6.16: U16.36@2467.13,1336.57 2467.13,1247.55 C84.1@2490,1224.68 2462.16,1196.84 2462.16,1093.59 Y1.3@2500.28,1055.47
N15602572: R118.1 U16.32 | length 257
  BOTTOM w6.16: U16.32@2530.12,1336.57 2530.12,1307.88 2543,1295 2565,1295 2595,1265 2595,1154.68 R118.1@2570,1129.68
N15602600: R117.2 R121.2 R122.1 | length 87.4
  TOP w6.16: R122.1@2530,1129.68 v1(2530,1158.52) R121.2@2530,1190.32
  BOTTOM w6.16: v1(2530,1158.52) R117.2@2530,1185.32
N15603170: C85.1 J14.1 | length 157.2
  BOTTOM w20: J14.1@3208.13,2527.52 C85.1@3365.32,2527.52
N15605512: R98.1 U16.39 | length 126.3
  BOTTOM w6.16: R98.1@2385,1224.68 2410,1249.68 2410,1286.5 2417.21,1293.71 2417.21,1294.2 2419.88,1296.87 U16.39@2419.88,1336.57
N15605755: C79.1 C80.1 R89.1 R92.1 U16.28 | length 459.6
  BOTTOM w8: U16.28@2573.43,1395.63 2638.74,1395.63
  BOTTOM w12: 2638.74,1395.63 2669.37,1365 2873.29,1365 2890.32,1347.97 C80.1@2890.32,1345 C79.1@2890.32,1305 R92.1@2890.32,1265 R89.1@2890.32,1225
N15611443: C118.1 R141.2 U21.4 | length 133.5
  BOTTOM w6.16: U21.4@4839.21,3132.4 C118.1@4900.32,3132.4 R141.2@4900.32,3060
N15611553: R144.1 U21.3 | length 72
  BOTTOM w6.16: R144.1@4670,3135.32 4672.92,3132.4 U21.3@4740.79,3132.4
N15653247: C124.1 R150.2 U25.4 | length 224.6
  BOTTOM w8: U25.4@680.79,2317.6 652.76,2317.6 645,2309.84 645,2232.76 652.76,2225 C124.1@710.32,2225 R150.2@710.32,2185
N15653357: R153.1 U25.3 | length 98.4
  BOTTOM w6.16: R153.1@749.68,2265 735,2279.68 735,2309.99 742.61,2317.6 U25.3@779.21,2317.6
N15653957: C121.1 R147.2 U24.4 | length 141.2
  BOTTOM w6.16: U24.4@4224.21,3132.4 4282.6,3132.4 4295,3120 C121.1@4295,3094.68 R147.2@4335,3094.68
N15654067: R148.1 U24.3 | length 165.5
  BOTTOM w6.16: U24.3@4125.79,3132.4 4087.6,3132.4 4074.99,3145.01 4074.99,3169.99 4085,3180 R148.1@4155.32,3180
N15659726: C18.2 R7.2 R8.1 U3.5 | length 145.2
  TOP w8: v1(210,1845) 205,1850 C18.2@205,1875.32 R8.1@245,1875.32 R7.2@285,1875.32
  BOTTOM w8: U3.5@177.24,1845 v1(210,1845)
N15752445: L9.1 U26.G1 U26.G2 U26.G3 U26.G4 | length 1499.4
  TOP w30: U26.G3@2542.81,2567.05 U26.G4@2542.81,2921.39
  ART03 w30: U26.G2@2286.9,2819.02 2286.9,3023.78 2323.12,3060 2506.59,3060 2542.81,3023.78 U26.G4@2542.81,2921.39
  BOTTOM w30: U26.G1@2286.9,2445 U26.G2@2286.9,2819.02 ; U26.G4@2542.81,2921.39 2545,2923.58 L9.1@2545,3098.5
N15772454: J19.14 R162.2 | length 118.9
  TOP w6.16: R162.2@5006.68,1615 5050,1615 5069.52,1595.48 J19.14@5117.47,1595.48
N15774097: J18.14 R161.2 | length 500.6
  TOP w6.16: J18.14@5117.47,2465.48 5222.31,2465.48 5257.68,2430.11 v1(5257.68,2371.69)
  BOTTOM w6.16: R161.2@5079.68,2235 5170,2235 5190,2255 5190,2345 5196.4,2351.4 5237.39,2351.4 v1(5257.68,2371.69)
N15830872: C190.2 J25.3 J25.5 Z9.2 | length 1045.3
  TOP w8: v1(1120,2485.24) C190.2@1200,2485.24
  BOTTOM w8: v1(1120,2485.24) 1105.32,2499.92 Z9.2@1105.32,2535 1105.32,2569.68 1065.72,2609.28 1065.72,2693.08 1102.64,2730 1335.8,2730 1347.39,2729.99 1385,2767.6 1385,2898 1409,2922 1449.96,2922 1465.96,2906 J25.5@1465.96,2857.16 1473.84,2857.16 J25.3@1544.7,2786.3
N15830941: C189.2 J25.2 R218.2 Z8.2 | length 1263.8
  TOP w8: C189.2@930,2485.24 v1(1041.26,2485.24)
  BOTTOM w8: v1(1041.26,2485.24) 1054.68,2498.66 Z8.2@1054.68,2535 1054.68,2565.32 1033.72,2586.28 1033.72,2704.72 1087,2758 1335.8,2758 1357,2779.2 1357,2912.43 1406.57,2962 1503.87,2962 J25.2@1544.7,3002.83 1697.49,3002.83 R218.2@1735.32,2965
N15838979: J25.4 R217.2 | length 268.7
  BOTTOM w10: R217.2@1320,2484.68 1320,2595 1349.88,2624.88 J25.4@1465.96,2624.88
N15851038: C185.1 R215.2 R216.1 | length 80.5
  TOP w10: R215.2@1425,2270.32 C185.1@1465,2270.32 1465.32,2270 R216.1@1505.32,2270
N15852295: J29.1 R223.2 | length 217.4
  BOTTOM w10: J29.1@1132.48,2669.29 1140.72,2669.29 1174,2636.01 1174,2493.68 R223.2@1160,2479.68
N15852481: J29.2 R224.2 | length 202.5
  BOTTOM w10: R224.2@1200,2479.68 1190,2489.68 1190,2648.07 J29.2@1211.22,2669.29
N15980269: J10.2 R73.2 | length 90.6
  TOP w10: R73.2@2776.5,400 2776.5,328.5 J10.2@2790,315
N16735828: LED1.1 R45.1 | length 75
  TOP w6.16: LED1.1@5015,315.31 R45.1@5015,390.32
N16735933: LED2.1 R48.1 | length 75
  TOP w6.16: LED2.1@4915,315.31 R48.1@4915,390.32
N16793147: D12.2 J9.1 R60.2 | length 244.5
  BOTTOM w6.16: R60.2@4604.68,580 4627.68,557 4681.68,557 D12.2@4704.68,580 4723.26,561.42 J9.1@4822.41,561.42
N16793149: D16.2 J9.7 R64.2 | length 239.4
  BOTTOM w6.16: R64.2@4604.68,815 4627.68,792 4681.68,792 D16.2@4704.68,815 4710.94,821.26 J9.7@4822.41,821.26
N16793151: D15.2 J9.5 R63.2 | length 250.6
  BOTTOM w6.16: R63.2@4604.68,770 4626.68,748 4682.68,748 D15.2@4704.68,770 4740.03,734.65 J9.5@4822.41,734.65
N16793153: D14.2 J9.3 R62.2 | length 245.9
  BOTTOM w6.16: R62.2@4604.68,670 4627.68,647 4681.68,647 D14.2@4704.68,670 4726.65,648.03 J9.3@4822.41,648.03
N16793155: D13.2 J9.2 R61.2 | length 244.4
  BOTTOM w6.16: R61.2@4604.68,625 4626.68,603 4682.68,603 D13.2@4704.68,625 4724.95,604.73 J9.2@4822.41,604.73
N16793157: D17.2 J9.8 R65.2 | length 237.8
  BOTTOM w6.16: R65.2@4604.68,860 4626.68,838 4682.68,838 D17.2@4704.68,860 4709.25,864.57 J9.8@4822.41,864.57
N16793300: D18.2 J9.9 R66.2 | length 237.1
  BOTTOM w6.16: R66.2@4604.68,905 4626.68,883 4682.68,883 D18.2@4704.68,905 4707.56,907.88 J9.9@4822.41,907.88
N16795570: LED3.1 R49.1 | length 75
  TOP w6.16: LED3.1@4815,315.31 R49.1@4815,390.32
N16795883: C37.2 R23.2 R24.2 R25.1 U5.5 | length 267.2
  TOP w6.16: R25.1@125,2264.68 125,2360 v1(135,2370)
  TOP w8: R23.2@85,2264.68 R25.1@125,2264.68 C37.2@165,2264.68 R24.2@205,2264.68
  BOTTOM w8: U5.5@135,2332.24 v1(135,2370)
N16811933: J24.1 R208.2 R209.2 | length 152.2
  TOP w6.16: v1(4566.99,2417.5) J24.1@4566.99,2490.88
  BOTTOM w6.16: R209.2@4512.5,2450.32 R208.2@4552.5,2450.32 4566.99,2435.83 v1(4566.99,2417.5)
N16823854: J24.7 R210.2 | length 106.2
  TOP w6.16: v1(4472.5,2417.5) J24.7@4472.5,2490.88
  BOTTOM w6.16: v1(4472.5,2417.5) R210.2@4472.5,2450.32
N16928945: J24.20 R211.1 | length 154.7
  TOP w6.16: J24.20@4141.79,2168.04 4141.79,2017.89 R211.1@4145,2014.68
N16929135: J24.22 R212.1 | length 155.6
  TOP w6.16: R212.1@4105,2014.68 4110.29,2019.97 J24.22@4110.29,2168.04
N16980859: C178.1 R201.2 U37.2 U38.6 | length 743.5
  BOTTOM w6.16: R201.2@4484.68,950 C178.1@4565.32,950 4595.32,980 4689.99,980 4699.65,989.66 U38.6@4699.65,1012.62 4699.65,1065.36 4672,1093.01 4672,1267 4697,1292 4761.84,1292 4774.16,1304.32 4774.16,1357.84 4786.48,1370.16 U37.2@4821.25,1370.16
N16980861: C177.1 R202.2 U37.3 U38.4 | length 716
  BOTTOM w6.16: R202.2@4565,1035.32 C177.1@4605,1035.32 4627.7,1012.62 U38.4@4660.27,1012.62 ; U38.4@4660.27,1012.62 4660.28,1054.72 4632,1083 4632,1292 4672,1332 4726,1332 4736.9,1342.9 4736.9,1440.51 4749.28,1452.89 4765.89,1452.89 4783.16,1470.16 U37.3@4821.25,1470.16
N16980863: C176.1 R200.2 R204.2 U37.7 U38.5 | length 835.7
  BOTTOM w6.16: R204.2@4445,1035.32 R200.2@4485,1035.32 C176.1@4525,1035.32 4525,1005 4537.87,992.13 4572.45,992.13 ; 4572.48,992.16 4671.27,992.16 4679.96,1000.85 U38.5@4679.96,1012.62 4679.96,1060.04 4651,1089 4651,1281 4683,1313 4740.68,1313 4753,1325.32 4753,1396 4777.16,1420.16 U37.7@4821.25,1420.16
N17405290: C29.2 R20.2 R22.1 U5.4 | length 149.1
  BOTTOM w8: U5.4@97.6,2332.24 97.6,2397.92 R22.1@100,2400.32 R20.2@140,2400.32 C29.2@180,2400.32
N17423559: C19.1 U4.6
N17423580: C19.2 L2.1 U4.2
N17423608: C27.2 R14.2 R15.1 U4.5 | length 232.2
  TOP w8: R14.2@364.68,1915 R15.1@364.68,1875 C27.2@364.68,1835 470,1835 v1(480,1845)
  BOTTOM w8: U4.5@447.24,1845 v1(480,1845)
N17423737: C20.2 R11.2 R13.1 U4.4 | length 154.2
  BOTTOM w8: U4.4@447.24,1882.4 517.72,1882.4 R13.1@520.32,1885 R11.2@520.32,1845 C20.2@520.32,1805
N17430242: R34.1 U7.3 | length 72.2
  BOTTOM w6.16: R34.1@304.68,1325 307.28,1322.4 U7.3@375.79,1322.4
N17430314: C47.1 R33.2 U7.4 | length 148.5
  BOTTOM w6.16: U7.4@474.21,1322.4 C47.1@550.32,1322.4 R33.2@550.32,1250
N17443353: R32.1 U6.3 | length 74.3
  BOTTOM w6.16: R32.1@304.68,1175 324,1175 331.6,1167.4 U6.3@375.79,1167.4
N17443371: C41.1 R31.2 U6.4 | length 145.1
  BOTTOM w6.16: U6.4@474.21,1167.4 C41.1@550.32,1167.4 R31.2@550.32,1098.42
N17444423: C38.2 Q4.1 Q5.1 Q6.3 R27.2 | length 657.2
  BOTTOM w6.16: R27.2@810,1379.68 R27.2@810.32,1380
  BOTTOM w8: Q5.1@468.5,1457.5 471,1455 550.32,1455 575.32,1480 731,1480 Q4.1@753.5,1457.5 787.82,1457.5 C38.2@810.32,1435 R27.2@810.32,1380 ; Q6.3@673.5,1275 673.5,1335.84 683.66,1346 800.84,1346 810,1355.16 R27.2@810,1379.68
N17444523: Q6.1 R29.2 R30.1 | length 129.3
  BOTTOM w6.16: Q6.1@753.5,1312.5 R30.1@810.32,1312.5 R29.2@810.32,1240
N17454508: C71.2 U13.1 | length 275.9
  BOTTOM w6.16: C71.2@1485,500.32 1485,472.32 1497.32,460 1572.48,460 1584.8,472.32 U13.1@1584.8,610.2
N17454513: C71.1 U13.3 | length 70.6
  BOTTOM w6.16: U13.3@1484.8,610.2 1485,610 C71.1@1485,539.68
N17455367: C72.2 U13.4 | length 70.6
  BOTTOM w6.16: C72.2@1435,539.68 1435,610 U13.4@1435.2,610.2
N17455372: C72.1 U13.5 | length 152.9
  BOTTOM w6.16: U13.5@1384.8,610.2 1384.8,512.64 1397.12,500.32 C72.1@1435,500.32
N17455499: C70.1 U13.6 | length 70.6
  BOTTOM w6.16: C70.1@1335,539.68 1335.2,539.88 U13.6@1335.2,610.2
N17455508: C68.1 U13.2 | length 70.5
  BOTTOM w6.16: C68.1@1535.2,539.68 U13.2@1535.2,610.2
N17466585: L4.1 U16.30 | length 35.4
  BOTTOM w8: U16.30@2573.43,1364.13 2595.87,1364.13 2605,1355
N17592125: C168.1 U36.6
N17592129: C168.2 L10.1 U36.2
